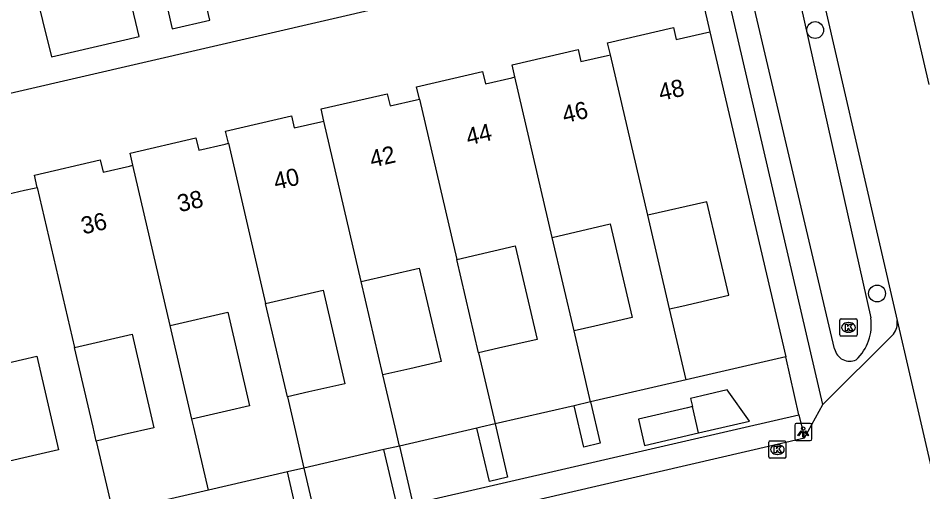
# Model space of a CAD drawing. Extents: x 156414 to 157775, y 382335 to 383765.
# Drawn here: x 156904.1 to 156956.7, y 382746.2 to 382773.8 of the extents above; entities that cross this region are included whole.
import ezdxf

# ---------------------------------------------------------------- set-up
doc = ezdxf.new("R2010")
doc.units = 0
for name, color, linetype in [('IMGEO_Boom', 7, 'Continuous'), ('IMGEO_Greppel_droge_sloot', 7, 'Continuous'), ('IMGEO_Kolk', 7, 'Continuous'), ('IMGEO_Lichtpunt', 7, 'Continuous'), ('IMGEO_Pand', 7, 'Continuous'), ('IMGEO_Pand_nummerreeks', 7, 'Continuous'), ('IMGEO_Rijbaan_lokaal_gesloten', 7, 'Continuous'), ('IMGEO_Rijbaan_lokaal_open', 7, 'Continuous'), ('IMGEO_Voetpad_open', 7, 'Continuous')]:
    doc.layers.add(name, color=color, linetype=linetype)

msp = doc.modelspace()

# ---------------------------------------------------------------- linework, layer by layer
at = {"layer": 'IMGEO_Boom'}
for centre in [(156950.436, 382773.105), (156954.034, 382757.777)]:
    msp.add_circle(centre, 0.489, dxfattribs=at)
at = {"layer": 'IMGEO_Greppel_droge_sloot'}
for points in [[(156949.139, 382776.615), (156953.67, 382756.361)], [(156951.569, 382754.553), (156946.518, 382776.011)]]:
    msp.add_lwpolyline(points, dxfattribs=at)
for centre, radius, start, end in [((156950.905, 382755.953), 2.795, 313.3335, 8.3941), ((156952.452, 382754.744), 0.903, 192.1935, 294.2386)]:
    msp.add_arc(centre, radius, start, end, dxfattribs=at)
at = {"layer": 'IMGEO_Kolk'}
for p, q in [((156951.874, 382755.38), (156951.874, 382756.232)), ((156951.949, 382756.306), (156952.801, 382756.306)), ((156952.875, 382756.232), (156952.875, 382755.38)), ((156952.362, 382756.086), (156952.387, 382756.086)), ((156952.801, 382755.306), (156951.949, 382755.306)), ((156952.385, 382755.526), (156952.36, 382755.526)), ((156947.741, 382748.277), (156947.741, 382749.129)), ((156947.816, 382749.203), (156948.668, 382749.203)), ((156948.229, 382748.983), (156948.254, 382748.983)), ((156948.742, 382749.129), (156948.742, 382748.277)), ((156948.252, 382748.423), (156948.227, 382748.423)), ((156948.668, 382748.203), (156947.816, 382748.203))]:
    msp.add_line(p, q, dxfattribs=at)
for points in [[(156951.874, 382755.38), (156951.874, 382756.232)], [(156951.949, 382756.306), (156952.801, 382756.306)], [(156952.875, 382756.232), (156952.875, 382755.38)], [(156952.195, 382756.006), (156952.318, 382756.006), (156952.318, 382755.855), (156952.448, 382756.006), (156952.612, 382756.006), (156952.466, 382755.855), (156952.619, 382755.606), (156952.467, 382755.606), (156952.382, 382755.77), (156952.318, 382755.703), (156952.318, 382755.606), (156952.195, 382755.606), (156952.195, 382756.006)], [(156952.801, 382755.306), (156951.949, 382755.306)], [(156947.741, 382748.277), (156947.741, 382749.129)], [(156947.816, 382749.203), (156948.668, 382749.203)], [(156948.062, 382748.903), (156948.185, 382748.903), (156948.185, 382748.752), (156948.315, 382748.903), (156948.479, 382748.903), (156948.333, 382748.752), (156948.486, 382748.503), (156948.334, 382748.503), (156948.249, 382748.667), (156948.185, 382748.6), (156948.185, 382748.503), (156948.062, 382748.503), (156948.062, 382748.903)], [(156948.742, 382749.129), (156948.742, 382748.277)], [(156948.668, 382748.203), (156947.816, 382748.203)]]:
    msp.add_lwpolyline(points, dxfattribs=at)
for centre, start, end in [((156951.951, 382756.23), 91.552, 178.448), ((156951.951, 382756.23), 91.552, 178.448), ((156952.799, 382756.23), 1.552, 88.448), ((156952.799, 382756.23), 1.552, 88.448), ((156951.951, 382755.382), 181.552, 268.448), ((156951.951, 382755.382), 181.552, 268.448), ((156952.799, 382755.382), 271.552, 358.448), ((156952.799, 382755.382), 271.552, 358.448), ((156947.818, 382749.127), 91.552, 178.448), ((156947.818, 382749.127), 91.552, 178.448), ((156948.666, 382749.127), 1.552, 88.448), ((156948.666, 382749.127), 1.552, 88.448), ((156947.818, 382748.279), 181.552, 268.448), ((156947.818, 382748.279), 181.552, 268.448), ((156948.666, 382748.279), 271.552, 358.448), ((156948.666, 382748.279), 271.552, 358.448)]:
    msp.add_arc(centre, 0.0765, start, end, dxfattribs=at)
for centre, major_axis, ratio, start_param, end_param in [((156952.361, 382755.806), (-0.387, 0.002), 0.722429, 4.712389, 7.853982), ((156952.386, 382755.806), (-0.39, 0.002), 0.717154, 1.570796, 4.712389), ((156948.228, 382748.703), (-0.387, 0.002), 0.722429, 4.712389, 7.853982), ((156948.253, 382748.703), (-0.39, 0.002), 0.717154, 1.570796, 4.712389)]:
    msp.add_ellipse(centre, major_axis=major_axis, ratio=ratio, start_param=start_param, end_param=end_param, dxfattribs=at)
at = {"layer": 'IMGEO_Lichtpunt'}
for p, q in [((156949.247, 382750.125), (156949.247, 382749.318)), ((156949.247, 382750.125), (156949.247, 382749.318)), ((156950.149, 382750.22), (156949.341, 382750.22)), ((156950.149, 382750.22), (156949.341, 382750.22)), ((156950.243, 382749.318), (156950.243, 382750.125)), ((156950.243, 382749.318), (156950.243, 382750.125)), ((156949.341, 382749.224), (156950.149, 382749.224)), ((156949.341, 382749.224), (156950.149, 382749.224))]:
    msp.add_line(p, q, dxfattribs=at)
for points in [[(156949.621, 382749.789), (156949.66, 382749.761), (156949.472, 382749.499), (156949.434, 382749.526), (156949.621, 382749.789)], [(156949.723, 382749.741), (156949.77, 382749.741), (156949.77, 382749.419), (156949.723, 382749.419), (156949.723, 382749.741)], [(156949.833, 382749.761), (156949.871, 382749.788), (156950.058, 382749.526), (156950.019, 382749.498), (156949.833, 382749.761)]]:
    msp.add_lwpolyline(points, dxfattribs=at)
msp.add_circle((156949.746, 382749.923), 0.0994, dxfattribs=at)
for centre, start, end in [((156949.341, 382750.125), 90, 180), ((156949.341, 382750.125), 90, 180), ((156950.149, 382750.125), 0, 90), ((156950.149, 382750.125), 0, 90), ((156949.341, 382749.318), 180, 270), ((156949.341, 382749.318), 180, 270), ((156950.149, 382749.318), 270, 0), ((156950.149, 382749.318), 270, 360)]:
    msp.add_arc(centre, 0.0946, start, end, dxfattribs=at)
at = {"layer": 'IMGEO_Pand'}
for points in [[(156938.538, 382771.663), (156938.374, 382772.369), (156942.206, 382773.257), (156942.368, 382772.55), (156944.322, 382773.001)], [(156944.322, 382773.001), (156948.732, 382754.094)], [(156932.989, 382770.377), (156932.824, 382771.085), (156936.666, 382771.976), (156936.828, 382771.269), (156938.363, 382771.623), (156938.538, 382771.663)], [(156940.712, 382762.328), (156938.538, 382771.663)], [(156927.439, 382769.091), (156927.275, 382769.796), (156931.11, 382770.688), (156931.272, 382769.981), (156932.807, 382770.335), (156932.989, 382770.377)], [(156935.161, 382761.046), (156932.989, 382770.377)], [(156921.889, 382767.805), (156921.724, 382768.516), (156925.571, 382769.404), (156925.733, 382768.697), (156927.268, 382769.051), (156927.439, 382769.091)], [(156927.439, 382769.091), (156929.609, 382759.764)], [(156916.34, 382766.518), (156916.175, 382767.227), (156920.006, 382768.115), (156920.168, 382767.408), (156921.703, 382767.762), (156921.889, 382767.805)], [(156924.058, 382758.481), (156921.889, 382767.805)], [(156910.789, 382765.238), (156910.625, 382765.944), (156914.455, 382766.828), (156914.617, 382766.121), (156916.152, 382766.475), (156916.34, 382766.518)], [(156916.34, 382766.518), (156918.507, 382757.199)], [(156905.238, 382763.956), (156905.075, 382764.66), (156908.899, 382765.547), (156909.061, 382764.84), (156910.596, 382765.194), (156910.789, 382765.238)], [(156912.956, 382755.917), (156910.789, 382765.238)], [(156899.689, 382762.669), (156899.524, 382763.379), (156903.353, 382764.267), (156903.515, 382763.559), (156904.501, 382763.786), (156905.05, 382763.913), (156905.238, 382763.956)], [(156905.238, 382763.956), (156907.404, 382754.635)], [(156941.979, 382756.889), (156942.681, 382757.051), (156945.416, 382757.683), (156944.15, 382763.122), (156940.712, 382762.328)], [(156941.979, 382756.889), (156940.712, 382762.328)], [(156935.161, 382761.046), (156938.53, 382761.824), (156939.796, 382756.385), (156937.641, 382755.888), (156936.427, 382755.607)], [(156936.427, 382755.607), (156935.161, 382761.046)], [(156929.609, 382759.764), (156933.012, 382760.549), (156934.277, 382755.111), (156932.031, 382754.593), (156930.874, 382754.325)], [(156930.874, 382754.325), (156929.609, 382759.764)], [(156924.058, 382758.481), (156927.433, 382759.261), (156928.698, 382753.823), (156926.876, 382753.402), (156925.323, 382753.044)], [(156925.323, 382753.044), (156924.058, 382758.481)], [(156918.507, 382757.199), (156921.849, 382757.971), (156923.114, 382752.534), (156921.021, 382752.051), (156919.771, 382751.762)], [(156912.956, 382755.917), (156916.3, 382756.689), (156917.564, 382751.252), (156916.23, 382750.944), (156914.219, 382750.48)], [(156919.771, 382751.762), (156918.507, 382757.199)], [(156942.941, 382752.756), (156941.979, 382756.889)], [(156914.219, 382750.48), (156912.956, 382755.917)], [(156907.404, 382754.635), (156910.743, 382755.406), (156912.006, 382749.969), (156910.294, 382749.574), (156908.667, 382749.199)], [(156937.389, 382751.474), (156936.427, 382755.607)], [(156908.667, 382749.199), (156908.481, 382750), (156907.404, 382754.635)], [(156901.852, 382753.352), (156905.209, 382754.128), (156906.471, 382748.692), (156905.213, 382748.402), (156903.115, 382747.917)], [(156930.874, 382754.325), (156931.836, 382750.192)], [(156948.732, 382754.094), (156942.941, 382752.756)], [(156926.285, 382748.909), (156926.031, 382750), (156925.323, 382753.044)], [(156942.941, 382752.756), (156937.389, 382751.474)], [(156943.659, 382749.671), (156946.615, 382750.36), (156945.329, 382752.177), (156943.852, 382751.833), (156943.192, 382751.679), (156943.304, 382751.198)], [(156919.771, 382751.762), (156920.181, 382750), (156920.733, 382747.627)], [(156937.389, 382751.474), (156937.949, 382749.068), (156937, 382748.847), (156936.439, 382751.255)], [(156937.389, 382751.474), (156936.439, 382751.255)], [(156936.439, 382751.255), (156931.836, 382750.192)], [(156943.304, 382751.198), (156943.019, 382751.132), (156940.167, 382750.468), (156940.522, 382748.941), (156943.659, 382749.671)], [(156943.659, 382749.671), (156943.304, 382751.198)], [(156915.181, 382746.345), (156914.331, 382750), (156914.219, 382750.48)], [(156930.785, 382749.949), (156926.285, 382748.909)], [(156931.836, 382750.192), (156932.558, 382747.088), (156931.508, 382746.844), (156930.785, 382749.949)], [(156931.836, 382750.192), (156931.007, 382750), (156930.785, 382749.949)], [(156908.667, 382749.199), (156909.629, 382745.062)], [(156926.285, 382748.909), (156927.008, 382745.804), (156926.102, 382745.593), (156925.379, 382748.7)], [(156926.285, 382748.909), (156925.379, 382748.7)], [(156925.379, 382748.7), (156920.733, 382747.627)], [(156919.767, 382747.404), (156915.181, 382746.345)], [(156920.733, 382747.627), (156921.463, 382744.487), (156920.498, 382744.262), (156919.767, 382747.404)], [(156920.733, 382747.627), (156919.767, 382747.404)], [(156915.181, 382746.345), (156909.629, 382745.062)]]:
    msp.add_lwpolyline(points, dxfattribs=at)
at = {"layer": 'IMGEO_Rijbaan_lokaal_gesloten'}
for points in [[(156949.716, 382780.032), (156955.201, 382756.216)], [(156957.069, 382769.94), (156955.879, 382775.053)], [(156955.201, 382756.216), (156956.633, 382750), (156958.351, 382742.538)]]:
    msp.add_lwpolyline(points, dxfattribs=at)
at = {"layer": 'IMGEO_Rijbaan_lokaal_open'}
for points in [[(156950.885, 382751.332), (156954.997, 382755.422)], [(156949.815, 382749.383), (156950.885, 382751.332)], [(156730.522, 382698.738), (156791.204, 382712.755), (156805.031, 382715.955), (156830.401, 382721.812), (156868.803, 382730.665), (156879.275, 382733.088), (156907.413, 382739.578), (156929.495, 382744.678), (156949.815, 382749.383)]]:
    msp.add_lwpolyline(points, dxfattribs=at)
msp.add_arc((156954.115, 382756.072), 1.096, 323.6233, 7.5584, dxfattribs=at)
at = {"layer": 'IMGEO_Voetpad_open'}
for points in [[(156950.885, 382751.332), (156944.502, 382778.816), (156949.317, 382779.939), (156949.716, 382780.032)], [(156943.044, 382778.552), (156872.472, 382762.194)], [(156943.044, 382778.552), (156944.322, 382773.001)], [(156912.102, 382777.424), (156913.074, 382773.174), (156915.257, 382773.68), (156914.277, 382777.927)], [(156905.015, 382775.784), (156906.054, 382771.545), (156911.155, 382772.729), (156910.148, 382776.972)], [(156949.496, 382750.719), (156948.732, 382754.094)], [(156878.945, 382734.453), (156946.378, 382750), (156949.496, 382750.719)], [(156949.496, 382750.719), (156949.815, 382749.383)]]:
    msp.add_lwpolyline(points, dxfattribs=at)

# ---------------------------------------------------------------- texts
at = {"layer": 'IMGEO_Pand_nummerreeks'}
for s, p in [('48', (156941.463, 382768.973)), ('46', (156935.868, 382767.679)), ('44', (156930.277, 382766.386)), ('42', (156924.682, 382765.091)), ('40', (156919.097, 382763.798)), ('38', (156913.505, 382762.505)), ('36', (156907.911, 382761.211))]:
    msp.add_text(s, height=1, rotation=13.0291, dxfattribs=at).set_placement(p)

doc.saveas('drawing.dxf')
